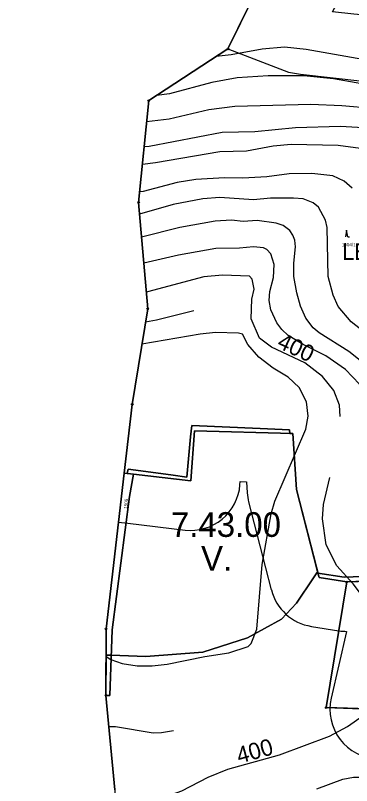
# Model space of a CAD drawing. Extents: x -706130 to -698555, y -971544 to -967260.
# Drawn here: x -705263.8 to -705059.5, y -970935.8 to -970468.1 of the extents above; entities that cross this region are included whole.
import ezdxf

# ---------------------------------------------------------------- set-up
doc = ezdxf.new("R2010")
doc.units = 0
for name, color, linetype in [('BPEJ hranice S', 7, 'Continuous'), ('BPEJ I-II trida ochrany S', 7, 'Continuous'), ('BPEJ kód', 7, 'Continuous'), ('Hranice řešeného území', 7, 'Continuous'), ('KN_Hranice obce', 7, 'Continuous'), ('KN_Hranice_katastrální území', 7, 'Continuous'), ('KN_Hranice_parcel', 7, 'Continuous'), ('KN_Parcelni cisla', 7, 'Continuous'), ('KN_Polygon parcely', 7, 'Continuous'), ('KN_POZEMKY_10_LESNI POZEMEK', 7, 'Continuous'), ('KN_POZEMKY_2_ORNA PUDA', 7, 'Continuous'), ('KN_Značky bodu BP', 7, 'Continuous'), ('KN_Značky kultur', 7, 'Continuous'), ('OP lesa 30 m', 7, 'Continuous'), ('Plochy lesní všeobecné S', 7, 'Continuous'), ('Plochy zemědělské všeobecné CELEK S', 7, 'Continuous'), ('Povodi vodniho toku S', 7, 'Continuous'), ('Regulační bloky v krajině S', 7, 'Continuous'), ('Regulační kódy v krajině S', 7, 'Continuous'), ('USES_BK_nadregionalni S', 7, 'Continuous'), ('USES_ŠRAFY S', 7, 'Continuous'), ('VÝŠKOPIS_vrstevnice doplňková', 7, 'Continuous'), ('VÝŠKOPIS_vrstevnice hlavní', 7, 'Continuous'), ('VÝŠKOPIS_vrstevnice výška', 7, 'Continuous'), ('VÝŠKOPIS_vrstevnice zesílená', 7, 'Continuous')]:
    doc.layers.add(name, color=color, linetype=linetype)

msp = doc.modelspace()

# ---------------------------------------------------------------- linework, layer by layer
at = {"layer": 'BPEJ hranice S'}
for points in [[(-705084.02, -970319.62), (-705082.33, -970361.23), (-705095.94, -970406.5), (-705096.72, -970409.11), (-705098.19, -970413.99), (-705134.66, -970488.39), (-705182.81, -970519.84), (-705188.93, -970581.69), (-705183.4, -970646.27), (-705192.86, -970704.33), (-705197.72, -970746.08)], [(-705208.77, -970856.58), (-705205.56, -970856.7), (-705184.54, -970857.47), (-705149.85, -970854.76), (-705122.75, -970846.08), (-705102.15, -970834.7), (-705092.94, -970824.94), (-705082.71, -970809.71), (-705080.66, -970806.65), (-705080.17, -970805.88), (-705093.02, -970756.09), (-705095.13, -970722.06), (-705097.02, -970722.01), (-705097.17, -970719.7), (-705115.07, -970718.89), (-705156.7, -970717.09), (-705157.37, -970723.99), (-705159.73, -970748.46), (-705168.01, -970747.34), (-705181.48, -970745.52), (-705195.4, -970743.73), (-705195.82, -970746.3), (-705197.72, -970746.08)], [(-705197.72, -970746.08), (-705195.82, -970746.3), (-705195.4, -970743.73), (-705181.48, -970745.52), (-705168.01, -970747.34), (-705159.73, -970748.46), (-705157.37, -970723.99), (-705156.7, -970717.09), (-705115.07, -970718.89), (-705097.17, -970719.7), (-705097.02, -970722.01), (-705095.13, -970722.06), (-705093.02, -970756.09), (-705080.17, -970805.88), (-705079.95, -970806.76), (-705064.07, -970809.28), (-705042.28, -970808.5)], [(-705197.72, -970746.08), (-705208.74, -970840.66), (-705208.77, -970856.58)], [(-705042.28, -970808.5), (-705064.07, -970809.28), (-705079.95, -970806.76), (-705080.17, -970805.88), (-705080.66, -970806.65), (-705082.71, -970809.71), (-705092.94, -970824.94), (-705102.15, -970834.7), (-705122.75, -970846.08), (-705149.85, -970854.76), (-705184.54, -970857.47), (-705205.56, -970856.7), (-705208.77, -970856.58)], [(-705208.77, -970856.58), (-705208.82, -970881.05), (-705203.39, -970938.45), (-705202.51, -970968.41), (-705195.17, -970984.83), (-705171.5, -971023.43), (-705158.96, -971097.02), (-705157.72, -971104.29), (-705155.35, -971118.19), (-705137.68, -971187.49), (-705125.34, -971235.85), (-705115.12, -971253.34), (-705092.92, -971276.14), (-705067.49, -971294.58)]]:
    msp.add_lwpolyline(points, dxfattribs=at)
at = {"layer": 'BPEJ I-II trida ochrany S'}
for p, q in [((-705080.66, -970806.65), (-705082.71, -970809.71)), ((-705080.17, -970805.88), (-705080.66, -970806.65)), ((-705079.95, -970806.76), (-705080.17, -970805.88)), ((-705079.24, -970809.5), (-705079.95, -970806.76)), ((-705079.95, -970806.76), (-705079.95, -970806.76)), ((-705062.48, -970812.16), (-705079.24, -970809.5)), ((-705024.44, -970810.62), (-705062.48, -970812.16)), ((-705102.15, -970834.7), (-705122.75, -970846.08)), ((-705208.77, -970856.58), (-705208.82, -970881.05)), ((-705208.82, -970881.05), (-705203.39, -970938.45))]:
    msp.add_line(p, q, dxfattribs=at)
for points in [[(-705082.71, -970809.71), (-705092.94, -970824.94), (-705102.15, -970834.7)], [(-705122.75, -970846.08), (-705149.85, -970854.76), (-705184.54, -970857.47), (-705205.55, -970856.7)], [(-705205.55, -970856.7), (-705205.56, -970856.7), (-705208.77, -970856.58)]]:
    msp.add_lwpolyline(points, dxfattribs=at)
at = {"layer": 'Hranice řešeného území'}
msp.add_lwpolyline([(-705203.39, -970938.45), (-705208.82, -970881.05), (-705208.74, -970840.66), (-705197.72, -970746.08), (-705192.86, -970704.33), (-705183.4, -970646.27), (-705188.93, -970581.69), (-705182.81, -970519.84), (-705134.66, -970488.39), (-705098.19, -970413.99), (-705096.72, -970409.11), (-705095.94, -970406.5), (-705082.33, -970361.23), (-705084.02, -970319.62), (-705071.49, -970267.29), (-705029.52, -970157.19), (-705074.04, -970140.3), (-705096.1, -970117.59), (-705174.6, -970073.33), (-705225.5, -970018.87), (-705263.84, -969987.56)], dxfattribs=at)
at = {"layer": 'KN_Hranice obce'}
msp.add_lwpolyline([(-705263.84, -969987.56), (-705225.5, -970018.87), (-705174.6, -970073.33), (-705096.1, -970117.59), (-705074.04, -970140.3), (-705029.52, -970157.19), (-705071.49, -970267.29), (-705084.02, -970319.62), (-705082.33, -970361.23), (-705095.94, -970406.5), (-705096.72, -970409.11), (-705098.19, -970413.99), (-705134.66, -970488.39), (-705182.81, -970519.84), (-705188.93, -970581.69), (-705183.4, -970646.27), (-705192.86, -970704.33), (-705197.72, -970746.08), (-705208.74, -970840.66), (-705208.82, -970881.05), (-705203.39, -970938.45)], dxfattribs=at)
at = {"layer": 'KN_Hranice_katastrální území'}
msp.add_lwpolyline([(-705263.84, -969987.56), (-705225.5, -970018.87), (-705174.6, -970073.33), (-705096.1, -970117.59), (-705074.04, -970140.3), (-705029.52, -970157.19), (-705071.49, -970267.29), (-705084.02, -970319.62), (-705082.33, -970361.23), (-705095.94, -970406.5), (-705096.72, -970409.11), (-705098.19, -970413.99), (-705134.66, -970488.39), (-705182.81, -970519.84), (-705188.93, -970581.69), (-705183.4, -970646.27), (-705192.86, -970704.33), (-705197.72, -970746.08), (-705208.74, -970840.66), (-705208.82, -970881.05), (-705203.39, -970938.45)], dxfattribs=at)
at = {"layer": 'KN_Hranice_parcel'}
for p, q in [((-705192.86, -970704.33), (-705197.72, -970746.08)), ((-705197.72, -970746.08), (-705208.74, -970840.66)), ((-705192.03, -970746.74), (-705197.72, -970746.08)), ((-705024.44, -970810.62), (-705062.48, -970812.16)), ((-705208.74, -970840.66), (-705208.82, -970881.05)), ((-705208.82, -970881.05), (-705203.39, -970938.45))]:
    msp.add_line(p, q, dxfattribs=at)
for points in [[(-705096.72, -970409.11), (-705098.19, -970413.99), (-705134.66, -970488.39), (-705182.81, -970519.84)], [(-705182.81, -970519.84), (-705188.93, -970581.69), (-705183.4, -970646.27), (-705192.86, -970704.33)], [(-705062.48, -970812.16), (-705079.24, -970809.5), (-705093.02, -970756.09), (-705095.13, -970722.06), (-705154.94, -970720.44), (-705157.26, -970750.81), (-705192.03, -970746.74)], [(-705208.82, -970881.05), (-705206.36, -970881.05), (-705205.04, -970841.14), (-705194.44, -970760.35), (-705192.03, -970746.74)], [(-705042.7, -970889.51), (-705074.93, -970888.47), (-705062.48, -970812.16)]]:
    msp.add_lwpolyline(points, dxfattribs=at)
at = {"layer": 'KN_Polygon parcely'}
for points in [[(-705098.19, -970413.99), (-705134.66, -970488.39), (-705182.81, -970519.84), (-705188.93, -970581.69), (-705183.4, -970646.27), (-705192.86, -970704.33), (-705197.72, -970746.08), (-705192.03, -970746.74), (-705157.26, -970750.81), (-705154.94, -970720.44), (-705095.13, -970722.06), (-705093.02, -970756.09), (-705079.24, -970809.5), (-705062.48, -970812.16), (-705024.44, -970810.62)], [(-704822.85, -970967.55), (-704823.85, -970899.66), (-704845.22, -970898.59), (-704874.14, -970906.79), (-704909.51, -970908.05), (-704934.96, -970910.32), (-704934.74, -970906.33), (-704937.47, -970906.61), (-705038.69, -970889.93), (-705042.7, -970889.51), (-705074.93, -970888.47), (-705062.48, -970812.16), (-705079.24, -970809.5), (-705093.02, -970756.09), (-705095.13, -970722.06), (-705154.94, -970720.44), (-705157.26, -970750.81), (-705192.03, -970746.74), (-705194.44, -970760.35), (-705205.04, -970841.14), (-705206.36, -970881.05), (-705208.82, -970881.05), (-705203.39, -970938.45)]]:
    msp.add_lwpolyline(points, dxfattribs=at)
for points in [[(-705194.44, -970760.35), (-705192.03, -970746.74), (-705197.72, -970746.08), (-705208.74, -970840.66), (-705208.82, -970881.05), (-705206.36, -970881.05), (-705205.04, -970841.14)], [(-705024.44, -970810.62), (-705062.48, -970812.16), (-705074.93, -970888.47), (-705042.7, -970889.51)]]:
    msp.add_lwpolyline(points, close=True, dxfattribs=at)
at = {"layer": 'KN_POZEMKY_10_LESNI POZEMEK'}
for p, q in [((-705134.66, -970488.39), (-705098.19, -970413.99)), ((-705182.81, -970519.84), (-705134.66, -970488.39)), ((-705188.93, -970581.69), (-705182.81, -970519.84)), ((-705183.4, -970646.27), (-705188.93, -970581.69)), ((-705192.86, -970704.33), (-705183.4, -970646.27)), ((-705197.72, -970746.08), (-705192.86, -970704.33)), ((-705154.94, -970720.44), (-705157.26, -970750.81)), ((-705095.13, -970722.06), (-705154.94, -970720.44)), ((-705093.02, -970756.09), (-705095.13, -970722.06)), ((-705192.03, -970746.74), (-705197.72, -970746.08)), ((-705157.26, -970750.81), (-705192.03, -970746.74)), ((-705079.24, -970809.5), (-705093.02, -970756.09)), ((-705062.48, -970812.16), (-705079.24, -970809.5)), ((-705024.44, -970810.62), (-705062.48, -970812.16))]:
    msp.add_line(p, q, dxfattribs=at)
at = {"layer": 'KN_POZEMKY_2_ORNA PUDA'}
for p, q in [((-705157.26, -970750.81), (-705154.94, -970720.44)), ((-705154.94, -970720.44), (-705095.13, -970722.06)), ((-705095.13, -970722.06), (-705093.02, -970756.09)), ((-705208.74, -970840.66), (-705197.72, -970746.08)), ((-705197.72, -970746.08), (-705192.03, -970746.74)), ((-705194.44, -970760.35), (-705192.03, -970746.74)), ((-705192.03, -970746.74), (-705194.44, -970760.35)), ((-705192.03, -970746.74), (-705157.26, -970750.81)), ((-705093.02, -970756.09), (-705079.24, -970809.5)), ((-705205.04, -970841.14), (-705194.44, -970760.35)), ((-705194.44, -970760.35), (-705205.04, -970841.14)), ((-705079.24, -970809.5), (-705062.48, -970812.16)), ((-705074.93, -970888.47), (-705062.48, -970812.16)), ((-705062.48, -970812.16), (-705074.93, -970888.47)), ((-705062.48, -970812.16), (-705024.44, -970810.62)), ((-705208.82, -970881.05), (-705208.74, -970840.66)), ((-705206.36, -970881.05), (-705205.04, -970841.14)), ((-705205.04, -970841.14), (-705206.36, -970881.05)), ((-705203.39, -970938.45), (-705208.82, -970881.05)), ((-705208.82, -970881.05), (-705206.36, -970881.05)), ((-705206.36, -970881.05), (-705208.82, -970881.05)), ((-705042.7, -970889.51), (-705074.93, -970888.47)), ((-705074.93, -970888.47), (-705042.7, -970889.51))]:
    msp.add_line(p, q, dxfattribs=at)
at = {"layer": 'KN_Značky bodu BP'}
for centre, radius in [((-705134.66, -970488.39), 0.5), ((-705134.66, -970488.39), 0.0303), ((-705182.81, -970519.84), 0.5), ((-705182.81, -970519.84), 0.0303), ((-705188.93, -970581.69), 0.5), ((-705188.93, -970581.69), 0.0303), ((-705183.4, -970646.27), 0.5), ((-705183.4, -970646.27), 0.0303), ((-705192.86, -970704.33), 0.5), ((-705192.86, -970704.33), 0.0303), ((-705062.48, -970812.16), 0.5), ((-705062.48, -970812.16), 0.0303), ((-705208.74, -970840.66), 0.5), ((-705208.74, -970840.66), 0.0303), ((-705208.82, -970881.05), 0.5), ((-705208.82, -970881.05), 0.0303), ((-705074.93, -970888.47), 0.5), ((-705074.93, -970888.47), 0.0303)]:
    msp.add_circle(centre, radius, dxfattribs=at)
at = {"layer": 'KN_Značky kultur'}
for p, q in [((-705062.51, -970598.61), (-705063.26, -970602.61)), ((-705061.76, -970602.61), (-705062.51, -970598.61)), ((-705061.76, -970602.61), (-705060.76, -970602.61))]:
    msp.add_line(p, q, dxfattribs=at)
at = {"layer": 'OP lesa 30 m'}
for p, q in [((-705122.07, -970763.58), (-705108.29, -970816.99)), ((-705083.94, -970839.13), (-705067.18, -970841.79)), ((-705062.53, -970842.16), (-705071.93, -970882.75))]:
    msp.add_line(p, q, dxfattribs=at)
for points in [[(-705127.35, -970753.1), (-705127.2, -970751.2), (-705123.37, -970751.31), (-705122.96, -970757.95)], [(-705201.18, -970775.88), (-705195.5, -970776.54), (-705160.75, -970780.61)]]:
    msp.add_lwpolyline(points, dxfattribs=at)
for centre, start, end in [((-705157.26, -970750.81), 263.3236, 355.6316), ((-705093.02, -970756.09), 183.548, 194.467), ((-705197.72, -970746.08), 263.3541, 263.3837), ((-705079.24, -970809.5), 194.467, 260.9817), ((-705062.48, -970812.16), 260.9817, 269.898), ((-705042.7, -970889.51), 166.9677, 267.8739)]:
    msp.add_arc(centre, 30, start, end, dxfattribs=at)
at = {"layer": 'Plochy lesní všeobecné S'}
for p, q in [((-705098.19, -970413.99), (-705134.66, -970488.39)), ((-705134.66, -970488.39), (-705182.81, -970519.84)), ((-705182.81, -970519.84), (-705188.93, -970581.69)), ((-705188.93, -970581.69), (-705183.4, -970646.27)), ((-705183.4, -970646.27), (-705192.86, -970704.33)), ((-705192.86, -970704.33), (-705197.72, -970746.08)), ((-705157.26, -970750.81), (-705154.94, -970720.44)), ((-705154.94, -970720.44), (-705095.13, -970722.06)), ((-705095.13, -970722.06), (-705093.02, -970756.09)), ((-705197.72, -970746.08), (-705192.03, -970746.74)), ((-705192.03, -970746.74), (-705157.26, -970750.81)), ((-705093.02, -970756.09), (-705079.24, -970809.5)), ((-705079.24, -970809.5), (-705062.48, -970812.16)), ((-705062.48, -970812.16), (-705024.44, -970810.62))]:
    msp.add_line(p, q, dxfattribs=at)
at = {"layer": 'Plochy zemědělské všeobecné CELEK S'}
for p, q in [((-705154.94, -970720.44), (-705157.26, -970750.81)), ((-705095.13, -970722.06), (-705154.94, -970720.44)), ((-705093.02, -970756.09), (-705095.13, -970722.06)), ((-705192.03, -970746.74), (-705197.72, -970746.08)), ((-705157.26, -970750.81), (-705192.03, -970746.74)), ((-705079.24, -970809.5), (-705093.02, -970756.09)), ((-705062.48, -970812.16), (-705079.24, -970809.5)), ((-705024.44, -970810.62), (-705062.48, -970812.16))]:
    msp.add_line(p, q, dxfattribs=at)
msp.add_lwpolyline([(-705197.72, -970746.08), (-705208.74, -970840.66), (-705208.82, -970881.05), (-705203.39, -970938.45)], dxfattribs=at)
at = {"layer": 'Povodi vodniho toku S'}
msp.add_lwpolyline([(-705263.84, -969987.56), (-705225.5, -970018.87), (-705174.6, -970073.33), (-705096.1, -970117.59), (-705074.04, -970140.3), (-705029.52, -970157.19), (-705071.49, -970267.29), (-705084.02, -970319.62), (-705082.33, -970361.23), (-705095.94, -970406.5), (-705096.72, -970409.11), (-705098.19, -970413.99), (-705134.66, -970488.39), (-705182.81, -970519.84), (-705188.93, -970581.69), (-705183.4, -970646.27), (-705192.86, -970704.33), (-705197.72, -970746.08), (-705208.74, -970840.66), (-705208.82, -970881.05), (-705203.39, -970938.45)], dxfattribs=at)
at = {"layer": 'Regulační bloky v krajině S'}
for p, q in [((-705098.19, -970413.99), (-705134.66, -970488.39)), ((-705134.66, -970488.39), (-705182.81, -970519.84)), ((-705182.81, -970519.84), (-705188.93, -970581.69)), ((-705188.93, -970581.69), (-705183.4, -970646.27)), ((-705183.4, -970646.27), (-705192.86, -970704.33)), ((-705192.86, -970704.33), (-705197.72, -970746.08)), ((-705157.26, -970750.81), (-705154.94, -970720.44)), ((-705154.94, -970720.44), (-705157.26, -970750.81)), ((-705154.94, -970720.44), (-705095.13, -970722.06)), ((-705095.13, -970722.06), (-705154.94, -970720.44)), ((-705095.13, -970722.06), (-705093.02, -970756.09)), ((-705093.02, -970756.09), (-705095.13, -970722.06)), ((-705197.72, -970746.08), (-705192.03, -970746.74)), ((-705192.03, -970746.74), (-705197.72, -970746.08)), ((-705192.03, -970746.74), (-705157.26, -970750.81)), ((-705157.26, -970750.81), (-705192.03, -970746.74)), ((-705093.02, -970756.09), (-705079.24, -970809.5)), ((-705079.24, -970809.5), (-705093.02, -970756.09)), ((-705079.24, -970809.5), (-705062.48, -970812.16)), ((-705062.48, -970812.16), (-705079.24, -970809.5)), ((-705062.48, -970812.16), (-705024.44, -970810.62)), ((-705024.44, -970810.62), (-705062.48, -970812.16))]:
    msp.add_line(p, q, dxfattribs=at)
msp.add_lwpolyline([(-705197.72, -970746.08), (-705208.74, -970840.66), (-705208.82, -970881.05), (-705203.39, -970938.45)], dxfattribs=at)
at = {"layer": 'USES_BK_nadregionalni S'}
msp.add_lwpolyline([(-705042.96, -970468.75), (-705058.24, -970467.41), (-705071.1, -970465.84), (-705045.1, -970418.13), (-705048.89, -970416.82), (-705079.26, -970412.42), (-705096.72, -970409.11), (-705098.19, -970413.99), (-705134.66, -970488.39), (-705097.9, -970502.49), (-705090.53, -970503.78), (-705052.65, -970507.93), (-704910.05, -970564.87), (-704857.47, -970584.94), (-704848.24, -970587.17), (-704869.42, -970702.1), (-704829.92, -970737.1), (-704827.39, -970702.43), (-704805.32, -970573.53), (-704802.61, -970560.73), (-704801.8, -970557.23), (-704845.38, -970546.71), (-704900.4, -970525), (-704904.79, -970523.27)], close=True, dxfattribs=at)
at = {"layer": 'USES_ŠRAFY S'}
msp.add_lwpolyline([(-705042.96, -970468.75), (-705058.24, -970467.41), (-705071.1, -970465.84), (-705045.1, -970418.13), (-705048.89, -970416.82), (-705079.26, -970412.42), (-705096.72, -970409.11), (-705098.19, -970413.99), (-705134.66, -970488.39), (-705097.9, -970502.49), (-705090.53, -970503.78), (-705052.65, -970507.93), (-704910.05, -970564.87), (-704857.47, -970584.94), (-704848.24, -970587.17), (-704869.42, -970702.1), (-704829.92, -970737.1), (-704827.39, -970702.43), (-704805.32, -970573.53), (-704802.61, -970560.73), (-704801.8, -970557.23), (-704845.38, -970546.71), (-704900.4, -970525), (-704904.79, -970523.27)], close=True, dxfattribs=at)
at = {"layer": 'VÝŠKOPIS_vrstevnice doplňková'}
for points in [[(-705155.48, -970647.46), (-705178.16, -970653.16), (-705184.72, -970654.39)], [(-705207.04, -970899.91), (-705202.99, -970899.84), (-705180.16, -970903.69), (-705175.02, -970903.55), (-705167.75, -970902.27)], [(-705080.58, -970937.79), (-705064.88, -970931.94), (-705058.32, -970930.8), (-705047.9, -970930.66), (-705043.62, -970932.09), (-705036.63, -970936.22)]]:
    msp.add_lwpolyline(points, dxfattribs=at)
at = {"layer": 'VÝŠKOPIS_vrstevnice hlavní'}
for points in [[(-705052.61, -970494.8), (-705087.14, -970488.81), (-705100.26, -970487.38), (-705113.96, -970488.52), (-705132.79, -970492.09), (-705141.87, -970493.1)], [(-704971.72, -970550.44), (-704975.86, -970543.59), (-704983.42, -970535.75), (-704992.12, -970529.61), (-705000.4, -970524.9), (-705012.38, -970519.77), (-705040.63, -970511.78), (-705070.59, -970506.64), (-705088.57, -970504.79), (-705110.25, -970504.79), (-705129.08, -970505.93), (-705144.49, -970508.78), (-705170.17, -970515.63), (-705178.14, -970516.79)], [(-705046.62, -970524.62), (-705065.45, -970522.91), (-705084.29, -970522.19), (-705130.51, -970523.33), (-705146.2, -970525.47), (-705170.46, -970531.18), (-705184.09, -970532.74)], [(-705042.34, -970537.03), (-705066.31, -970535.46), (-705093.7, -970536.46), (-705118.24, -970538.74), (-705138.22, -970539.17), (-705182.44, -970547.73), (-705185.59, -970547.92)], [(-705059.18, -970572.98), (-705064.03, -970568.7), (-705070.87, -970565.56), (-705083.71, -970564.14), (-705097.41, -970564.28), (-705110.96, -970566.13), (-705125.66, -970566.99), (-705136.79, -970566.7), (-705154.19, -970567.7), (-705165.61, -970569.56), (-705186.15, -970574.98), (-705188.3, -970575.3)], [(-705029.54, -970681.81), (-705034.92, -970674.56), (-705041.77, -970668.29), (-705059.75, -970654.16), (-705067.59, -970644.89), (-705070.73, -970638.04), (-705073.73, -970626.63), (-705074.44, -970596.95), (-705075.3, -970592.39), (-705079.72, -970584.54), (-705082.86, -970581.97), (-705088.85, -970579.55), (-705094.84, -970578.98), (-705108.82, -970579.12), (-705119.1, -970580.12), (-705139.64, -970578.69), (-705149.91, -970579.4), (-705167.89, -970582.97), (-705188.32, -970588.77)], [(-705043.61, -970688.56), (-705047.19, -970684.27), (-705053.33, -970678.42), (-705061.17, -970672.28), (-705079.15, -970660.87), (-705082.86, -970657.73), (-705087.28, -970651.88), (-705090.56, -970644.6), (-705092.85, -970636.61), (-705094.7, -970626.63), (-705094.7, -970618.64), (-705093.7, -970608.65), (-705093.99, -970604.66), (-705095.13, -970601.52), (-705097.13, -970598.66), (-705101.12, -970595.67), (-705105.4, -970594.24), (-705116.81, -970592.67), (-705125.37, -970593.24), (-705132.51, -970592.39), (-705142.5, -970592.96), (-705163.9, -970596.95), (-705187.12, -970602.8)], [(-705052.62, -970694.98), (-705054.61, -970691.97), (-705063.17, -970683.12), (-705075.15, -970674.85), (-705088.85, -970668), (-705097.98, -970662.44), (-705101.83, -970658.87), (-705104.97, -970654.88), (-705108.68, -970646.89), (-705109.68, -970641.18), (-705109.11, -970635.76), (-705106.97, -970627.2), (-705106.54, -970619.35), (-705108.54, -970612.93), (-705111.11, -970610.22), (-705112.96, -970609.22), (-705119.1, -970608.65), (-705127.66, -970609.51), (-705141.92, -970609.65), (-705164.75, -970613.79), (-705185.78, -970618.5)], [(-705208.77, -970857.52), (-705205.84, -970859.32), (-705198.99, -970861.75), (-705189.86, -970863.03), (-705180.73, -970863.03), (-705171.6, -970862.18), (-705148.77, -970857.33), (-705134.22, -970855.19), (-705122.38, -970851.33), (-705120.52, -970849.48), (-705117.1, -970840.92), (-705113.82, -970801.54), (-705108.4, -970770.72), (-705106.26, -970763.02), (-705087.42, -970719.36), (-705085.85, -970711.37), (-705086.85, -970702.81), (-705091.28, -970694.11), (-705097.98, -970687.69), (-705107.11, -970682.27), (-705115.96, -970675.71), (-705122.52, -970668), (-705125.8, -970661.58), (-705128.23, -970661.01), (-705142.21, -970660.58), (-705151.63, -970661.58), (-705186.91, -970667.82)]]:
    msp.add_lwpolyline(points, dxfattribs=at)
at = {"layer": 'VÝŠKOPIS_vrstevnice zesílená'}
for points in [[(-705044.91, -970550.16), (-705067.74, -970547.02), (-705096.27, -970546.45), (-705107.11, -970547.45), (-705123.38, -970550.44), (-705139.64, -970550.87), (-705178.73, -970557.57), (-705186.64, -970558.56)], [(-705066.47, -970711.67), (-705066.88, -970704.81), (-705070.3, -970695.82), (-705077.15, -970687.4), (-705087.85, -970679.13), (-705108.25, -970669.57), (-705115.53, -970664.01), (-705120.52, -970652.31), (-705120.1, -970640.32), (-705118.81, -970634.33), (-705119.95, -970628.34), (-705121.52, -970626.48), (-705137.93, -970625.91), (-705149.34, -970626.91), (-705183.58, -970636.04), (-705184.26, -970636.17)], [(-705038.83, -970845.62), (-705044.48, -970833.5), (-705048.62, -970826.37), (-705058.46, -970813.38), (-705068.45, -970802.4), (-705075.01, -970789.56), (-705077.15, -970773.86), (-705076.58, -970765.02), (-705072.77, -970748.67)], [(-705169.03, -970941.22), (-705162.75, -970938.93), (-705146.63, -970930.66), (-705134.79, -970925.81), (-705103.4, -970917.1), (-705072.87, -970905.83), (-705062.03, -970899.84), (-705052.48, -970893.17)]]:
    msp.add_lwpolyline(points, dxfattribs=at)

# ---------------------------------------------------------------- texts
at = {"layer": 'BPEJ kód'}
for s, p in [('7.43.00', (-705169.37, -970784.78)), ('V.', (-705151.01, -970805.33))]:
    msp.add_text(s, height=15, dxfattribs=at).set_placement(p)
at = {"layer": 'KN_Parcelni cisla'}
msp.add_text('1504/1', height=2, dxfattribs=at).set_placement((-705065.47, -970608.3))
msp.add_text('1505', height=2, rotation=84, dxfattribs=at).set_placement((-705195.93, -970767.83))
at = {"layer": 'Regulační kódy v krajině S'}
msp.add_text('LE', height=10, dxfattribs=at).set_placement((-705065.31, -970616.53))
at = {"layer": 'VÝŠKOPIS_vrstevnice výška'}
for rotation, p in [(334.8931, (-705105.43, -970669.51)), (15.4977, (-705127.85, -970922.59))]:
    msp.add_text('400', height=10, rotation=rotation, dxfattribs=at).set_placement(p)

doc.saveas('drawing.dxf')
